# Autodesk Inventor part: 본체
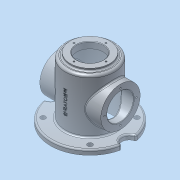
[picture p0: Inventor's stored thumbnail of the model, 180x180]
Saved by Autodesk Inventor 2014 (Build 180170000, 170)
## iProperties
Created: 2018-04
Part Number: 본체
Material: 알루미늄 6061
Document SubType Name: Modeling
Designer: net
Density: 2.71 g/cm^3
Appearance: 알루미늄 - 평지
Mass: 1151.3 g
Surface Area: 1200.36 cm^2
Volume: 424.833 cm^3
Author: net
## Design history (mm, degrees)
sketch "스케치1"
  geometry: L1 (0, 0)-(0, 140); L2 (50, 0)-(50, 8); L3 (50, 8)-(80, 8); L4 (80, 8)-(80, 18); L5 (80, 18)-(50, 18); L6 (50, 18)-(50, 128); L7 (50, 128)-(40, 128); L8 (27, 133)-(27, 120); L9 (27, 120)-(45, 120); L10 (45, 120)-(45, 0); L11 (40, 128)-(40, 133); L12 (40, 133)-(27, 133); L13 (45, 0)-(50, 0)
  constraints: 26 end point, 4 horizontal, 4 parallel, 2 perpendicular, 1 collinear, 1 horizontal alignment, 1 vertical
  dimensions: "d0" = 140 distance of L1.start L1.end; "d1" = 54 diameter of L8 L1; "d3" = 100 diameter of L6.end L1; "d5" = 8 distance of L2.start L2.end; "d6" = 100 diameter of L2 L1; "d7" = 10 distance of L3.end L4.end; "d8" = 160 diameter of L4 L1; "d11" = 13 distance of L8.start L8.end; "d13" = 90 diameter of L10 L1; "d14" = 80 diameter of L11 L1; "d15" = 133 vertical distance of L2.start L11.end; "d16" = 110 distance from line of L6.end L5
revolve "회전1" sketch "스케치1" stored, may be unused: angle "d17" = 90 deg
node "작업 평면1"
sketch "스케치2"
  geometry: L1 (0, 50)-(0, -50) reference; C1 r 40 at (68, 0); 2 further points
  constraints: 1 centre point, 1 horizontal alignment, 1 midpoint
  dimensions: "d19" = 68 distance from line of C1.centre L1; "d20" = 80 diameter of C1
extrude "돌출1" join sketch "스케치2" stored distance "d21" = 10; taper "d22" = 0 deg
sketch "스케치3"
  geometry: C1 r 40 at (0, 0) reference; C2 r 27 at (0, 0); 1 further point
  constraints: 1 centre point, 1 coincident
  dimensions: "d23" = 54 diameter of C2
extrude "돌출2" cut sketch "스케치3" stored distance "d24" = 0; taper "d25" = 0 deg
sketch "스케치4"
  geometry: C1 r 27 at (0, 0) reference; 2 further points
  constraints: 1 vertical alignment
  dimensions: "d26" = 32.5 distance of C1.centre point (0, 32.5)
hole "구멍1" sketch "스케치4" at (0, 32.5) diameter "d27" = 3.242; stored, may be unused: countersink angle "d31" = 90 deg, drill point angle "d33" = 118 deg; dims "d28" = 8, "d29" = 4, "d30" = 2, "d32" = 10
sketch "스케치5"
  geometry: 2 further points
  constraints: 1 vertical alignment
  dimensions: "d37" = 32.5 distance of point (0, 0) point (0, 32.5)
hole "구멍2" sketch "스케치5" at (0, 32.5) diameter "d38" = 3.242; stored, may be unused: countersink angle "d42" = 90 deg, drill point angle "d44" = 118 deg; dims "d39" = 8, "d40" = 4, "d41" = 2, "d43" = 10
fillet "모깎기1" dims "d48" = 3
chamfer "모따기1" distance "d49" = 1; stored, may be unused: second distance "d50" = 2, angle "d51" = 45 deg
chamfer "모따기2" distance "d52" = 1; stored, may be unused: second distance "d53" = 2, angle "d54" = 45 deg
fillet "모깎기2" dims "d55" = 3
fillet "모깎기3" dims "d56" = 3
fillet "모깎기4" dims "d57" = 3
fillet "모깎기5" dims "d58" = 5
sketch "스케치6"
  geometry: C1 r 15 at (-80, 0); C2 r 15 at (80, 0); A1 r 80 centre (0, 0) between (-80, 0) and (80, 0) reference; 1 further point
  constraints: 2 centre point, 2 horizontal alignment, 2 point on circle
  dimensions: "d59" = 30 diameter of C1; "d60" = 30 diameter of C2
extrude "돌출3" cut sketch "스케치6" distance "d61" = 10; taper "d62" = 0 deg
sketch "스케치7"
  geometry: L1 (0, 0)-(0, 73.406); L2 (-47.73, 47.73)-(0, 0)
  constraints: 4 end point, 1 vertical
  dimensions: "d63" = 45 deg angle of L1 L2; "d64" = 67.5 distance of L1.start L2.start
hole "구멍3" sketch "스케치7" at (-47.73, 47.73) diameter "d65" = 10; stored, may be unused: countersink angle "d69" = 90 deg, drill point angle "d71" = 118 deg; dims "d66" = 8, "d67" = 4, "d68" = 2, "d70" = 10
fillet "모깎기6" dims "d75" = 3
node "작업 평면2"
sketch "스케치8"
  geometry: 2 further points
  constraints: 1 vertical alignment, 1 other
  dimensions: "d77" = 70 distance of point (0, 0) point (0, 70)
fillet "모깎기7" dims "d78" = 3
feature "엠보싱1" dims "d79" = 0.5, "d80" = 0
node "솔리드1"
mirror "대칭1"
pattern_circular "원형 패턴1" dims angle "d35" = 360 deg
mirror "대칭2"
pattern_circular "원형 패턴2" dims angle "d46" = 360 deg
pattern_circular "원형 패턴3" dims angle "d73" = 360 deg
other parameters: "d18" = 62, "d76" = 75
